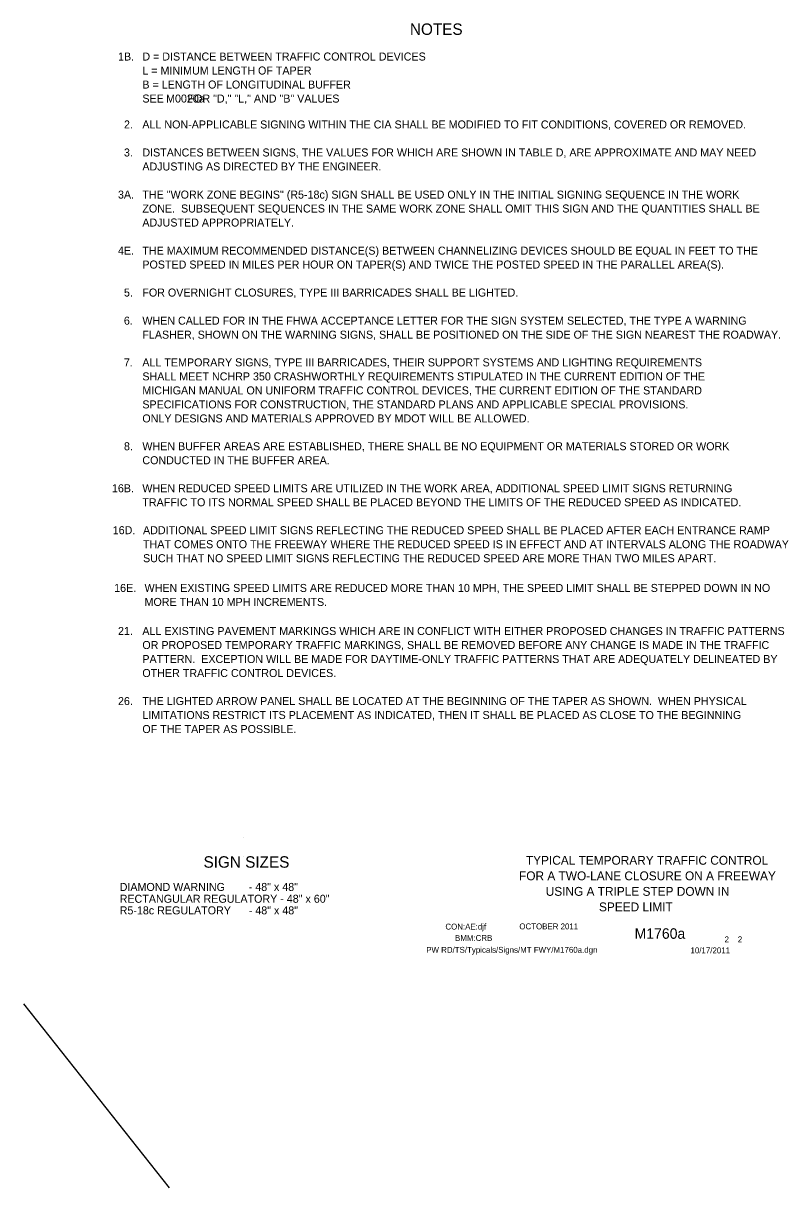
# Model space of a CAD drawing. Extents: x 16504 to 18480, y 5523 to 6928.
# Drawn here: x 17677 to 18480, y 5687 to 6909 of the extents above; entities that cross this region are included whole.
import ezdxf

# ---------------------------------------------------------------- set-up
doc = ezdxf.new("R2010")
doc.units = 0
for name, color, linetype in [('BORDER', 7, 'Continuous'), ('BORDER_SIGNAL_WO', 7, 'Continuous'), ('TYPICAL_TEXT_DIMEN_PR', 7, 'Continuous')]:
    doc.layers.add(name, color=color, linetype=linetype)

msp = doc.modelspace()

# ---------------------------------------------------------------- linework, layer by layer
at = {"layer": 'BORDER'}
for p, q in [((17907.5, 6055), (17907.5, 6055)), ((17907.5, 6035), (17907.5, 6035))]:
    msp.add_line(p, q, dxfattribs=at)
at = {"layer": 'TYPICAL_TEXT_DIMEN_PR'}
msp.add_line((17676.8, 5880), (17829.7, 5687.1), dxfattribs=at)

# ---------------------------------------------------------------- texts
at = {"layer": 'BORDER'}
for s, p in [('TYPICAL TEMPORARY TRAFFIC CONTROL', (18204.2, 6026.1)), ('FOR A TWO-LANE CLOSURE ON A FREEWAY', (18197, 6009.8)), ('USING A TRIPLE STEP DOWN IN', (18225, 5993.5)), ('SPEED LIMIT', (18280.9, 5977.2))]:
    msp.add_text(s, height=9.3, dxfattribs=at).set_placement(p)
at = {"layer": 'BORDER_SIGNAL_WO'}
for s, height, p in [('CON:AE:djf  ', 6.2, (18119.7, 5958.1)), ('    OCTOBER 2011', 6.2, (18188.1, 5958.3)), ('BMM:CRB', 6.2, (18129.8, 5946.2)), ('    M1760a   ', 11, (18301.9, 5948.4)), ('PW RD/TS/Typicals/Signs/MT FWY/M1760a.dgn      ', 6.2, (18099.6, 5933.7)), ('10/17/2011', 6.2, (18376.9, 5933.1)), (' 2    2 ', 6.2, (18410.4, 5944.7))]:
    msp.add_text(s, height=height, dxfattribs=at).set_placement(p)
at = {"layer": 'TYPICAL_TEXT_DIMEN_PR'}
for s, height, p in [('NOTES', 12, (18082.5, 6897)), ('1B.', 8.4, (17776.2, 6870.1)), ('D = DISTANCE BETWEEN TRAFFIC CONTROL DEVICES', 8.4, (17801.7, 6870.1)), ('L = MINIMUM LENGTH OF TAPER', 8.4, (17801.7, 6855.4)), ('B = LENGTH OF LONGITUDINAL BUFFER', 8.4, (17801.7, 6840.7)), ('SEE        FOR "D," "L," AND "B" VALUES', 8.4, (17801.7, 6826)), ('M0020a', 8.4, (17826.6, 6826)), ('2.', 8.4, (17782.4, 6798.8)), ('ALL NON-APPLICABLE SIGNING WITHIN THE CIA SHALL BE MODIFIED TO FIT CONDITIONS, COVERED OR REMOVED.', 8.4, (17801.7, 6798.8)), ('3.', 8.4, (17782.4, 6769.4)), ('DISTANCES BETWEEN SIGNS, THE VALUES FOR WHICH ARE SHOWN IN TABLE D, ARE APPROXIMATE AND MAY NEED', 8.4, (17801.7, 6769.4)), ('ADJUSTING AS DIRECTED BY THE ENGINEER.', 8.4, (17801.7, 6754.7)), ('3A.', 8.4, (17776.1, 6725.2)), ('THE "WORK ZONE BEGINS" (R5-18c) SIGN SHALL BE USED ONLY IN THE INITIAL SIGNING SEQUENCE IN THE WORK', 8.4, (17801.7, 6725.2)), ('ZONE.  SUBSEQUENT SEQUENCES IN THE SAME WORK ZONE SHALL OMIT THIS SIGN AND THE QUANTITIES SHALL BE', 8.4, (17801.7, 6710.6)), ('ADJUSTED APPROPRIATELY.', 8.4, (17801.7, 6695.9)), ('4E.', 8.4, (17776.1, 6666.4)), ('THE MAXIMUM RECOMMENDED DISTANCE(S) BETWEEN CHANNELIZING DEVICES SHOULD BE EQUAL IN FEET TO THE', 8.4, (17801.7, 6666.4)), ('POSTED SPEED IN MILES PER HOUR ON TAPER(S) AND TWICE THE POSTED SPEED IN THE PARALLEL AREA(S).', 8.4, (17801.7, 6651.8)), ('5.', 8.4, (17782.4, 6622.4)), ('FOR OVERNIGHT CLOSURES, TYPE III BARRICADES SHALL BE LIGHTED.', 8.4, (17801.7, 6622.4)), ('6.', 8.4, (17782.3, 6592.9)), ('WHEN CALLED FOR IN THE FHWA ACCEPTANCE LETTER FOR THE SIGN SYSTEM SELECTED, THE TYPE A WARNING ', 8.4, (17801.7, 6592.9)), ('FLASHER, SHOWN ON THE WARNING SIGNS, SHALL BE POSITIONED ON THE SIDE OF THE SIGN NEAREST THE ROADWAY.', 8.4, (17801.7, 6578.2)), ('7.', 8.4, (17782.3, 6549)), ('ALL TEMPORARY SIGNS, TYPE III BARRICADES, THEIR SUPPORT SYSTEMS AND LIGHTING REQUIREMENTS', 8.4, (17801.7, 6549.1)), ('SHALL MEET NCHRP 350 CRASHWORTHLY REQUIREMENTS STIPULATED IN THE CURRENT EDITION OF THE', 8.4, (17801.7, 6534.4)), ('MICHIGAN MANUAL ON UNIFORM TRAFFIC CONTROL DEVICES, THE CURRENT EDITION OF THE STANDARD', 8.4, (17801.7, 6519.7)), ('SPECIFICATIONS FOR CONSTRUCTION, THE STANDARD PLANS AND APPLICABLE SPECIAL PROVISIONS.', 8.4, (17801.7, 6505)), ('ONLY DESIGNS AND MATERIALS APPROVED BY MDOT WILL BE ALLOWED.', 8.4, (17801.7, 6490.3)), ('8.', 8.4, (17782.4, 6461.1)), ('WHEN BUFFER AREAS ARE ESTABLISHED, THERE SHALL BE NO EQUIPMENT OR MATERIALS STORED OR WORK     ', 8.4, (17801.7, 6461.1)), ('CONDUCTED IN THE BUFFER AREA.', 8.4, (17801.7, 6446.4)), ('16B.', 8.4, (17769.8, 6417)), ('WHEN REDUCED SPEED LIMITS ARE UTILIZED IN THE WORK AREA, ADDITIONAL SPEED LIMIT SIGNS RETURNING', 8.4, (17801.7, 6417)), ('TRAFFIC TO ITS NORMAL SPEED SHALL BE PLACED BEYOND THE LIMITS OF THE REDUCED SPEED AS INDICATED.', 8.4, (17801.7, 6402.3)), ('16D.', 8.4, (17770.6, 6373)), ('ADDITIONAL SPEED LIMIT SIGNS REFLECTING THE REDUCED SPEED SHALL BE PLACED AFTER EACH ENTRANCE RAMP', 8.4, (17802.4, 6373)), ('THAT COMES ONTO THE FREEWAY WHERE THE REDUCED SPEED IS IN EFFECT AND AT INTERVALS ALONG THE ROADWAY', 8.4, (17802.4, 6358.3)), ('SUCH THAT NO SPEED LIMIT SIGNS REFLECTING THE REDUCED SPEED ARE MORE THAN TWO MILES APART.', 8.4, (17802.4, 6343.6)), ('16E.', 8.4, (17772.1, 6312.4)), ('WHEN EXISTING SPEED LIMITS ARE REDUCED MORE THAN 10 MPH, THE SPEED LIMIT SHALL BE STEPPED DOWN IN NO', 8.4, (17804, 6312.4)), ('MORE THAN 10 MPH INCREMENTS.', 8.4, (17804, 6297.7)), ('21.', 8.4, (17776.1, 6267.2)), ('ALL EXISTING PAVEMENT MARKINGS WHICH ARE IN CONFLICT WITH EITHER PROPOSED CHANGES IN TRAFFIC PATTERNS', 8.4, (17801.7, 6267.2)), ('OR PROPOSED TEMPORARY TRAFFIC MARKINGS, SHALL BE REMOVED BEFORE ANY CHANGE IS MADE IN THE TRAFFIC', 8.4, (17801.7, 6252.5)), ('PATTERN.  EXCEPTION WILL BE MADE FOR DAYTIME-ONLY TRAFFIC PATTERNS THAT ARE ADEQUATELY DELINEATED BY', 8.4, (17801.7, 6237.8)), ('OTHER TRAFFIC CONTROL DEVICES.', 8.4, (17801.7, 6223.1)), ('26.', 8.4, (17776.1, 6193.7)), ('THE LIGHTED ARROW PANEL SHALL BE LOCATED AT THE BEGINNING OF THE TAPER AS SHOWN.  WHEN PHYSICAL', 8.4, (17801.7, 6193.7)), ('LIMITATIONS RESTRICT ITS PLACEMENT AS INDICATED, THEN IT SHALL BE PLACED AS CLOSE TO THE BEGINNING', 8.4, (17801.7, 6179)), ('OF THE TAPER AS POSSIBLE.', 8.4, (17801.7, 6164.3)), ('SIGN SIZES', 12, (17865.9, 6023)), ('DIAMOND WARNING        - 48" x 48"', 8.4, (17777.9, 5998.6)), ('RECTANGULAR REGULATORY - 48" x 60"', 8.4, (17777.9, 5986.2)), ('R5-18c REGULATORY      - 48" x 48"', 8.4, (17777.9, 5974))]:
    msp.add_text(s, height=height, dxfattribs=at).set_placement(p)

doc.saveas('drawing.dxf')
